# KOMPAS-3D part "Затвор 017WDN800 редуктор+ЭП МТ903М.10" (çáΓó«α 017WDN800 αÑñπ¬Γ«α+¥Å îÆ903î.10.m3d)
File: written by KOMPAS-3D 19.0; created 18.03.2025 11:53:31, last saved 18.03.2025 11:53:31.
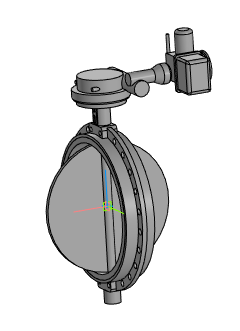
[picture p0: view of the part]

Document properties: Автор: Евгений; Полное имя файла: Затвор 017WDN800 редуктор+ЭП МТ903М.10.a3d

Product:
- Part/product: Затвор 017WDN800 редуктор+ЭП МТ903М.10
    Масса: 592.104

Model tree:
1. Операция без истории:1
